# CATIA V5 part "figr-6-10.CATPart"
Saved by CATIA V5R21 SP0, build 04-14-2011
Part number: Part1
Bounding box of the stored display mesh (mm): x -25 to 25, y -75 to 75, z 0 to 20
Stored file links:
  D:\CATIA V5R21 E-RESOURCES\CATIA-V5R21\catia-v5r21-prt\c06-catia-v5r21-prt\c06-catia-v5r21-figr-6-10.CATPart
  C:\Program Files\Dassault Systemes\B13\intel_a\reffiles\standard\MetricThinPitch.txt
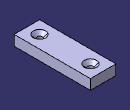
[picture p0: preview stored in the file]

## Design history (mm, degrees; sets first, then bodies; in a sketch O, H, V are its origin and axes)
Body1 (main body)
  Sketch1 on xy-plane, origin (0, 0, 0), H (1, 0, 0), V (0, 1, 0)
    line L1 (-25, 75) -> (25, 75)
    line L2 (25, 75) -> (25, -75)
    line L3 (25, -75) -> (-25, -75)
    line L4 (-25, -75) -> (-25, 75)
    axis line L5 (25, -75) -> (-25, 75)
    length L2 = 150
    length L3 = 50
    horizontal: L1 H, L3 H
    vertical: L2 V, L4 V
    midpoint: O L5
  Pad1: profile Sketch1, direction (0, 0, 1), length 20
  Sketch2 on face of Pad1, origin (-8.6664, -28.8348, 20), H (1, 0, 0), V (0, 1, 0)
    point P1 (8.6664, -21.1652)
    reference projected line E1 (-16.3336, -46.1652) -> (33.6664, -46.1652) from edge [face of Pad1 | face of Pad1]
    reference projected line E2 (-16.3336, 103.8348) -> (-16.3336, -46.1652) from edge [face of Pad1 | face of Pad1]
    distance P1 E1 = 25
    distance P1 E2 = 25
  Hole1: placed by Sketch2, at (0, -50, 20) direction (0, 0, -1), diameter 10.647, through (limit type 3), countersink depth 6, countersink angle 90
  Sketch3 on face of Pad1, origin (3.6925, 50.8892, 20), H (1, 0, 0), V (0, 1, 0)
    point P1 (-3.6925, -0.8892)
    reference projected line E1 (-28.6925, 24.1108) -> (-28.6925, -125.8892) from edge [face of Pad1 | face of Pad1]
    reference projected line E2 (21.3075, 24.1108) -> (-28.6925, 24.1108) from edge [face of Pad1 | face of Pad1]
    distance P1 E1 = 25
    distance E2 P1 = 25
  Hole2: placed by Sketch3, at (0, 50, 20) direction (0, 0, -1), diameter 10.647, through (limit type 3), countersink depth 6, countersink angle 90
